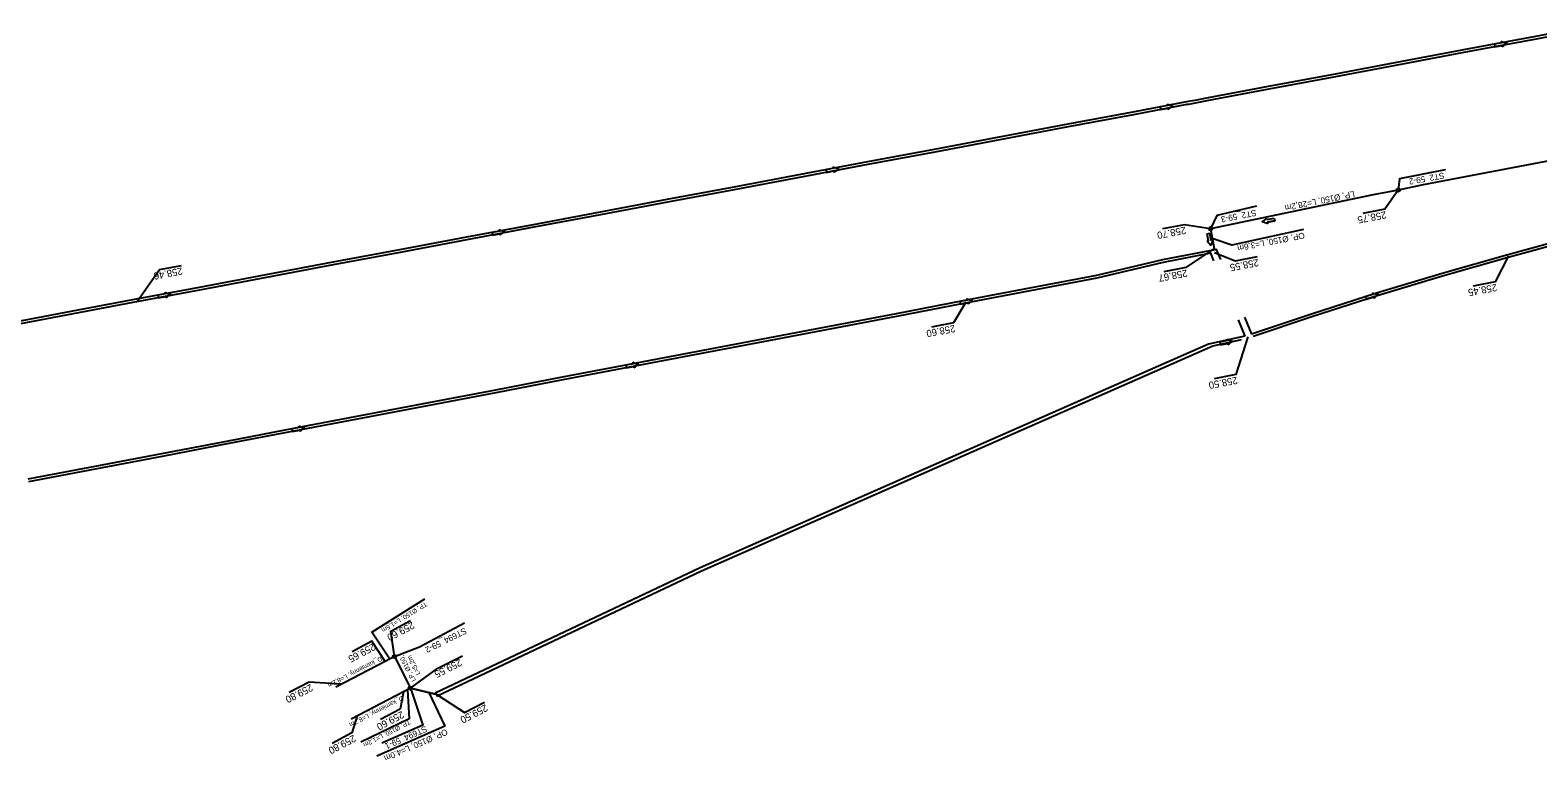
# Model space of a CAD drawing. Extents: x -1 to 65640748, y -22 to 5530284.
# Drawn here: x 6559740.8 to 6559962.5, y 5529060.7 to 5529168.1 of the extents above; entities that cross this region are included whole.
import ezdxf

# ---------------------------------------------------------------- set-up
doc = ezdxf.new("R2010")
doc.units = 0
for name, color, linetype in [('TOR_PROF-studnie i osadniki', 7, 'Continuous'), ('TOR_PS_ODW-drenaze', 7, 'Continuous'), ('TOR_PS_ODW-drenokolektory', 7, 'Continuous'), ('TOR_PS_ODW-kolektory', 7, 'Continuous'), ('TOR_PS_ODW-studnie PEHD', 7, 'Continuous'), ('TOR_PS_OPIS_O-opisy rurociagow', 7, 'Continuous'), ('TOR_PS_OPIS_O-opisy studni', 7, 'Continuous'), ('TOR_PS_OPIS_T-INFO', 7, 'Continuous'), ('TOR_PS_T-rowy otwarte umocnione', 7, 'Continuous')]:
    doc.layers.add(name, color=color, linetype=linetype)

msp = doc.modelspace()

# ---------------------------------------------------------------- linework, layer by layer
at = {"layer": 'TOR_PROF-studnie i osadniki'}
for centre, radius in [((6559941.99, 5529144.54), 0.25), ((6559941.99, 5529144.54), 0.125), ((6559914.39, 5529138.85), 0.25), ((6559914.39, 5529138.85), 0.125), ((6559794.35, 5529075.89), 0.25), ((6559794.35, 5529075.89), 0.125), ((6559796.7, 5529071.25), 0.25), ((6559796.7, 5529071.25), 0.125)]:
    msp.add_circle(centre, radius, dxfattribs=at)
at = {"layer": 'TOR_PS_ODW-drenaze'}
for p, q in [((6559792.99, 5529075.18), (6559785.73, 5529071.38)), ((6559795.69, 5529070.72), (6559787.98, 5529066.69))]:
    msp.add_line(p, q, dxfattribs=at)
at = {"layer": 'TOR_PS_ODW-drenokolektory'}
for p, q in [((6559794.35, 5529075.89), (6559792.99, 5529075.18)), ((6559796.7, 5529071.25), (6559795.69, 5529070.72))]:
    msp.add_line(p, q, dxfattribs=at)
for points in [[(6559999.28, 5529155.5), (6559945.65, 5529145.28), (6559941.99, 5529144.54)], [(6559941.99, 5529144.54), (6559938.33, 5529143.81), (6559914.39, 5529138.85)], [(6559794.35, 5529075.89), (6559796.7, 5529071.25), (6559796.7, 5529071.25)]]:
    msp.add_lwpolyline(points, dxfattribs=at)
at = {"layer": 'TOR_PS_ODW-kolektory'}
msp.add_line((6559796.7, 5529071.25), (6559800.58, 5529070.32), dxfattribs=at)
for points in [[(6559914.39, 5529138.85), (6559914.94, 5529135.94)], [(6559800.58, 5529070.32), (6559796.7, 5529071.25)]]:
    msp.add_lwpolyline(points, dxfattribs=at)
at = {"layer": 'TOR_PS_ODW-studnie PEHD'}
for centre, radius in [((6559941.99, 5529144.54), 0.25), ((6559941.99, 5529144.54), 0.112), ((6559794.35, 5529075.89), 0.25), ((6559794.35, 5529075.89), 0.112)]:
    msp.add_circle(centre, radius, dxfattribs=at)
at = {"layer": 'TOR_PS_OPIS_O-opisy rurociagow'}
for p, q in [((6559957.21, 5529166.2), (6559956.14, 5529166)), ((6559957.21, 5529166.2), (6559956.14, 5529166)), ((6559956.14, 5529166), (6559956.21, 5529165.61)), ((6559956.14, 5529166), (6559956.21, 5529165.61)), ((6559956.21, 5529165.61), (6559957.28, 5529165.81)), ((6559957.28, 5529165.81), (6559956.21, 5529165.61)), ((6559908.07, 5529156.97), (6559907, 5529156.77)), ((6559908.07, 5529156.97), (6559907, 5529156.77)), ((6559907, 5529156.77), (6559907.07, 5529156.37)), ((6559907, 5529156.77), (6559907.07, 5529156.37)), ((6559907.07, 5529156.37), (6559908.14, 5529156.58)), ((6559908.14, 5529156.58), (6559907.07, 5529156.37)), ((6559858.93, 5529147.74), (6559857.86, 5529147.53)), ((6559858.93, 5529147.74), (6559857.86, 5529147.53)), ((6559857.86, 5529147.53), (6559857.93, 5529147.14)), ((6559857.86, 5529147.53), (6559857.93, 5529147.14)), ((6559857.93, 5529147.14), (6559859, 5529147.34)), ((6559859, 5529147.34), (6559857.93, 5529147.14)), ((6559922.68, 5529140.19), (6559923.75, 5529140.41)), ((6559922.68, 5529140.19), (6559923.75, 5529140.41)), ((6559923.83, 5529140.02), (6559922.76, 5529139.8)), ((6559922.76, 5529139.8), (6559923.83, 5529140.02)), ((6559923.75, 5529140.41), (6559923.83, 5529140.02)), ((6559923.75, 5529140.41), (6559923.83, 5529140.02)), ((6559809.79, 5529138.5), (6559808.72, 5529138.3)), ((6559809.79, 5529138.5), (6559808.72, 5529138.3)), ((6559808.72, 5529138.3), (6559808.79, 5529137.91)), ((6559808.72, 5529138.3), (6559808.79, 5529137.91)), ((6559808.79, 5529137.91), (6559809.86, 5529138.11)), ((6559809.86, 5529138.11), (6559808.79, 5529137.91)), ((6559913.89, 5529138.09), (6559914.28, 5529138.17)), ((6559913.89, 5529138.09), (6559914.28, 5529138.17)), ((6559914.11, 5529137.02), (6559913.89, 5529138.09)), ((6559914.11, 5529137.02), (6559913.89, 5529138.09)), ((6559914.28, 5529138.17), (6559914.5, 5529137.1)), ((6559914.5, 5529137.1), (6559914.28, 5529138.17)), ((6559760.65, 5529129.27), (6559759.58, 5529129.07)), ((6559760.65, 5529129.27), (6559759.58, 5529129.07)), ((6559759.58, 5529129.07), (6559759.65, 5529128.68)), ((6559759.58, 5529129.07), (6559759.65, 5529128.68)), ((6559759.65, 5529128.68), (6559760.72, 5529128.88)), ((6559760.72, 5529128.88), (6559759.65, 5529128.68)), ((6559878.6, 5529128.34), (6559877.52, 5529128.13)), ((6559878.6, 5529128.34), (6559877.52, 5529128.13)), ((6559877.52, 5529128.13), (6559877.6, 5529127.74)), ((6559877.52, 5529128.13), (6559877.6, 5529127.74)), ((6559877.6, 5529127.74), (6559878.67, 5529127.94)), ((6559878.67, 5529127.94), (6559877.6, 5529127.74)), ((6559938.29, 5529129.19), (6559937.25, 5529128.87)), ((6559938.29, 5529129.19), (6559937.25, 5529128.87)), ((6559937.25, 5529128.87), (6559937.36, 5529128.49)), ((6559937.25, 5529128.87), (6559937.36, 5529128.49)), ((6559937.36, 5529128.49), (6559938.41, 5529128.8)), ((6559938.41, 5529128.8), (6559937.36, 5529128.49)), ((6559916.85, 5529122.38), (6559915.78, 5529122.17)), ((6559916.85, 5529122.38), (6559915.78, 5529122.17)), ((6559915.78, 5529122.17), (6559915.85, 5529121.78)), ((6559915.78, 5529122.17), (6559915.85, 5529121.78)), ((6559915.85, 5529121.78), (6559916.92, 5529121.98)), ((6559916.92, 5529121.98), (6559915.85, 5529121.78)), ((6559829.48, 5529118.97), (6559828.41, 5529118.77)), ((6559829.48, 5529118.97), (6559828.41, 5529118.77)), ((6559828.41, 5529118.77), (6559828.48, 5529118.37)), ((6559828.41, 5529118.77), (6559828.48, 5529118.37)), ((6559828.48, 5529118.37), (6559829.56, 5529118.58)), ((6559829.56, 5529118.58), (6559828.48, 5529118.37)), ((6559780.37, 5529109.61), (6559779.29, 5529109.4)), ((6559780.37, 5529109.61), (6559779.29, 5529109.4)), ((6559779.29, 5529109.4), (6559779.37, 5529109.01)), ((6559779.29, 5529109.4), (6559779.37, 5529109.01)), ((6559779.37, 5529109.01), (6559780.44, 5529109.21)), ((6559780.44, 5529109.21), (6559779.37, 5529109.01))]:
    msp.add_line(p, q, dxfattribs=at)
for points in [[(6559957.16, 5529166.42), (6559957.16, 5529166.42)], [(6559957.32, 5529165.59), (6559957.32, 5529165.59)], [(6559908.02, 5529157.19), (6559908.02, 5529157.19)], [(6559908.18, 5529156.35), (6559908.18, 5529156.35)], [(6559858.88, 5529147.96), (6559858.88, 5529147.96)], [(6559859.04, 5529147.12), (6559859.04, 5529147.12)], [(6559809.74, 5529138.72), (6559809.74, 5529138.72)], [(6559922.65, 5529140.42), (6559922.65, 5529140.42)], [(6559922.81, 5529139.58), (6559922.81, 5529139.58)], [(6559809.9, 5529137.89), (6559809.9, 5529137.89)], [(6559913.89, 5529136.98), (6559913.89, 5529136.98)], [(6559914.72, 5529137.16), (6559914.72, 5529137.16)], [(6559760.6, 5529129.49), (6559760.6, 5529129.49)], [(6559760.76, 5529128.66), (6559760.76, 5529128.66)], [(6559878.54, 5529128.56), (6559878.54, 5529128.56)], [(6559878.7, 5529127.72), (6559878.7, 5529127.72)], [(6559938.22, 5529129.4), (6559938.22, 5529129.4)], [(6559938.46, 5529128.59), (6559938.46, 5529128.59)], [(6559916.8, 5529122.59), (6559916.8, 5529122.59)], [(6559916.96, 5529121.76), (6559916.96, 5529121.76)], [(6559829.43, 5529119.19), (6559829.43, 5529119.19)], [(6559829.59, 5529118.36), (6559829.59, 5529118.36)], [(6559780.31, 5529109.82), (6559780.31, 5529109.82)], [(6559780.47, 5529108.99), (6559780.47, 5529108.99)]]:
    msp.add_lwpolyline(points, dxfattribs=at)
for centre, radius, start, end in [((6559959.09, 5529170.95), 4.92, 246.931, 257.3128), ((6559957.62, 5529166.41), 0.458, 179.0455, 207.5068), ((6559959.09, 5529170.95), 4.92, 246.931, 257.3128), ((6559957.62, 5529166.41), 0.458, 179.0455, 207.5068), ((6559957.74, 5529165.76), 0.458, 173.7749, 202.2361), ((6559957.74, 5529165.76), 0.458, 173.7749, 202.2361), ((6559960.75, 5529162.07), 4.92, 123.9689, 134.3507), ((6559960.75, 5529162.07), 4.92, 123.9689, 134.3507), ((6559909.95, 5529161.71), 4.92, 246.931, 257.3128), ((6559908.48, 5529157.18), 0.458, 179.0455, 207.5068), ((6559909.95, 5529161.71), 4.92, 246.931, 257.3128), ((6559908.48, 5529157.18), 0.458, 179.0455, 207.5068), ((6559908.6, 5529156.53), 0.458, 173.7749, 202.2361), ((6559908.6, 5529156.53), 0.458, 173.7749, 202.2361), ((6559911.61, 5529152.84), 4.92, 123.9689, 134.3507), ((6559911.61, 5529152.84), 4.92, 123.9689, 134.3507), ((6559860.81, 5529152.48), 4.92, 246.931, 257.3128), ((6559859.34, 5529147.95), 0.458, 179.0455, 207.5068), ((6559860.81, 5529152.48), 4.92, 246.931, 257.3128), ((6559859.34, 5529147.95), 0.458, 179.0455, 207.5068), ((6559862.47, 5529143.6), 4.92, 123.9689, 134.3507), ((6559862.47, 5529143.6), 4.92, 123.9689, 134.3507), ((6559859.46, 5529147.29), 0.458, 173.7749, 202.2361), ((6559859.46, 5529147.29), 0.458, 173.7749, 202.2361), ((6559811.67, 5529143.25), 4.92, 246.931, 257.3128), ((6559810.2, 5529138.72), 0.458, 179.0455, 207.5068), ((6559811.67, 5529143.25), 4.92, 246.931, 257.3128), ((6559810.2, 5529138.72), 0.458, 179.0455, 207.5068), ((6559919.16, 5529143.89), 4.92, 304.7037, 315.0855), ((6559919.16, 5529143.89), 4.92, 304.7037, 315.0855), ((6559920.95, 5529135.03), 4.92, 67.6658, 78.0476), ((6559920.95, 5529135.03), 4.92, 67.6658, 78.0476), ((6559922.23, 5529140.24), 0.458, 354.5097, 22.9709), ((6559922.23, 5529140.24), 0.458, 354.5097, 22.9709), ((6559922.36, 5529139.58), 0.458, 359.7803, 28.2416), ((6559922.36, 5529139.58), 0.458, 359.7803, 28.2416), ((6559810.32, 5529138.06), 0.458, 173.7749, 202.2361), ((6559810.32, 5529138.06), 0.458, 173.7749, 202.2361), ((6559813.33, 5529134.37), 4.92, 123.9689, 134.3507), ((6559813.33, 5529134.37), 4.92, 123.9689, 134.3507), ((6559914.07, 5529136.56), 0.458, 84.7749, 113.2361), ((6559914.07, 5529136.56), 0.458, 84.7749, 113.2361), ((6559910.43, 5529133.49), 4.92, 34.9689, 45.3507), ((6559910.43, 5529133.49), 4.92, 34.9689, 45.3507), ((6559919.28, 5529135.31), 4.92, 157.931, 168.3128), ((6559919.28, 5529135.31), 4.92, 157.931, 168.3128), ((6559914.72, 5529136.7), 0.458, 90.0456, 118.5068), ((6559914.72, 5529136.7), 0.458, 90.0456, 118.5068), ((6559762.53, 5529134.01), 4.92, 246.931, 257.3128), ((6559761.06, 5529129.48), 0.458, 179.0455, 207.5068), ((6559762.53, 5529134.01), 4.92, 246.931, 257.3128), ((6559761.06, 5529129.48), 0.458, 179.0455, 207.5068), ((6559761.18, 5529128.83), 0.458, 173.7749, 202.2361), ((6559761.18, 5529128.83), 0.458, 173.7749, 202.2361), ((6559764.19, 5529125.14), 4.92, 123.9689, 134.3507), ((6559764.19, 5529125.14), 4.92, 123.9689, 134.3507), ((6559880.46, 5529133.08), 4.92, 247.0634, 257.4452), ((6559879, 5529128.55), 0.458, 179.178, 207.6392), ((6559880.46, 5529133.08), 4.92, 247.0634, 257.4452), ((6559879, 5529128.55), 0.458, 179.178, 207.6392), ((6559879.13, 5529127.9), 0.458, 173.9073, 202.3686), ((6559879.13, 5529127.9), 0.458, 173.9073, 202.3686), ((6559882.15, 5529124.21), 4.92, 124.1013, 134.4831), ((6559882.15, 5529124.21), 4.92, 124.1013, 134.4831), ((6559939.65, 5529134.1), 4.92, 253.0777, 263.4595), ((6559938.67, 5529129.44), 0.458, 185.1922, 213.6535), ((6559939.65, 5529134.1), 4.92, 253.0777, 263.4595), ((6559938.67, 5529129.44), 0.458, 185.1922, 213.6535), ((6559938.87, 5529128.8), 0.458, 179.9216, 208.3828), ((6559938.87, 5529128.8), 0.458, 179.9216, 208.3828), ((6559942.26, 5529125.46), 4.92, 130.1156, 140.4974), ((6559942.26, 5529125.46), 4.92, 130.1156, 140.4974), ((6559918.72, 5529127.12), 4.92, 247.0234, 257.4052), ((6559917.26, 5529122.59), 0.458, 179.138, 207.5992), ((6559918.72, 5529127.12), 4.92, 247.0234, 257.4052), ((6559917.26, 5529122.59), 0.458, 179.138, 207.5992), ((6559917.38, 5529121.93), 0.458, 173.8673, 202.3285), ((6559917.38, 5529121.93), 0.458, 173.8673, 202.3285), ((6559920.4, 5529118.25), 4.92, 124.0613, 134.4431), ((6559920.4, 5529118.25), 4.92, 124.0613, 134.4431), ((6559831.34, 5529123.72), 4.92, 247.086, 257.4679), ((6559829.89, 5529119.18), 0.458, 179.2006, 207.6618), ((6559831.34, 5529123.72), 4.92, 247.086, 257.4679), ((6559829.89, 5529119.18), 0.458, 179.2006, 207.6618), ((6559833.04, 5529114.85), 4.92, 124.1239, 134.5057), ((6559833.04, 5529114.85), 4.92, 124.1239, 134.5057), ((6559830.01, 5529118.53), 0.458, 173.9299, 202.3912), ((6559830.01, 5529118.53), 0.458, 173.9299, 202.3912), ((6559782.23, 5529114.35), 4.92, 247.086, 257.4679), ((6559780.77, 5529109.82), 0.458, 179.2006, 207.6618), ((6559782.23, 5529114.35), 4.92, 247.086, 257.4679), ((6559780.77, 5529109.82), 0.458, 179.2006, 207.6618), ((6559780.9, 5529109.16), 0.458, 173.9299, 202.3912), ((6559780.9, 5529109.16), 0.458, 173.9299, 202.3912), ((6559783.92, 5529105.48), 4.92, 124.1239, 134.5057), ((6559783.92, 5529105.48), 4.92, 124.1239, 134.5057)]:
    msp.add_arc(centre, radius, start, end, dxfattribs=at)
at = {"layer": 'TOR_PS_OPIS_T-INFO'}
for points in [[(6559948.91, 5529147.52), (6559948.91, 5529147.52), (6559942.2, 5529146.19), (6559941.99, 5529144.54)], [(6559941.99, 5529144.54), (6559940.02, 5529141.72), (6559936.78, 5529141.09)], [(6559921.14, 5529142.14), (6559915.3, 5529140.8), (6559914.39, 5529138.85)], [(6559914.39, 5529138.85), (6559910.55, 5529139.44), (6559907.32, 5529138.82)], [(6559928.09, 5529138.73), (6559917.55, 5529136.43), (6559914.66, 5529137.4)], [(6559914.94, 5529135.94), (6559910.76, 5529133.13), (6559907.53, 5529132.51)], [(6559921.24, 5529134.7), (6559918.01, 5529134.07), (6559914.98, 5529135.32)], [(6559958.2, 5529134.84), (6559956.28, 5529131.03), (6559953.05, 5529130.41)], [(6559756.61, 5529128.3), (6559759.82, 5529132.85), (6559763.05, 5529133.45)], [(6559878.39, 5529128.03), (6559876.61, 5529124.99), (6559873.37, 5529124.37)], [(6559919.86, 5529122.92), (6559918.14, 5529117.38), (6559914.91, 5529116.76)], [(6559793.67, 5529075.53), (6559791.05, 5529079.49), (6559798.83, 5529084.41)], [(6559794.35, 5529075.89), (6559793.83, 5529079.65), (6559796.74, 5529081.19)], [(6559794.35, 5529075.89), (6559798.05, 5529077.33), (6559804.67, 5529080.84)], [(6559792.99, 5529075.18), (6559791.02, 5529078.14), (6559788.12, 5529076.58)], [(6559796.7, 5529071.25), (6559800.75, 5529074.19), (6559804.38, 5529075.99)], [(6559786.57, 5529071.82), (6559781.81, 5529072.14), (6559778.88, 5529070.62)], [(6559796.28, 5529070.98), (6559796.52, 5529066.75), (6559789.44, 5529063.28)], [(6559799.38, 5529070.71), (6559801.76, 5529065.63), (6559791.79, 5529061.22)], [(6559795.69, 5529070.72), (6559795.2, 5529068.17), (6559792.3, 5529066.61)], [(6559796.7, 5529071.25), (6559798.52, 5529065.81), (6559792.51, 5529063.16)], [(6559800.58, 5529070.32), (6559804.68, 5529067.68), (6559807.61, 5529069.18)], [(6559788.87, 5529067.16), (6559788.11, 5529064.66), (6559785.21, 5529063.11)]]:
    msp.add_lwpolyline(points, dxfattribs=at)
at = {"layer": 'TOR_PS_T-rowy otwarte umocnione'}
for p, q in [((6559918.44, 5529125.46), (6559919.44, 5529123.03)), ((6559919.37, 5529125.84), (6559920.4, 5529123.33)), ((6559839.32, 5529088.93), (6559800.34, 5529070.49)), ((6559839.53, 5529088.48), (6559800.55, 5529070.03))]:
    msp.add_line(p, q, dxfattribs=at)
for points in [[(6559967.11, 5529168.06), (6559962.2, 5529167.14), (6559952.37, 5529165.29), (6559942.54, 5529163.45), (6559932.71, 5529161.6), (6559922.88, 5529159.75), (6559914.04, 5529158.09), (6559913.06, 5529157.91), (6559912.07, 5529157.72), (6559911.09, 5529157.54), (6559910.85, 5529157.49), (6559910.85, 5529157.49), (6559903.23, 5529156.06), (6559893.4, 5529154.21), (6559883.57, 5529152.37), (6559873.74, 5529150.52), (6559863.92, 5529148.67), (6559854.09, 5529146.83), (6559844.26, 5529144.98), (6559834.43, 5529143.13), (6559824.6, 5529141.29), (6559814.78, 5529139.44), (6559804.95, 5529137.59), (6559795.12, 5529135.75), (6559785.29, 5529133.9), (6559775.46, 5529132.05), (6559765.63, 5529130.21), (6559755.81, 5529128.36), (6559745.98, 5529126.51), (6559736.15, 5529124.67)], [(6559967.18, 5529167.67), (6559962.27, 5529166.75), (6559952.44, 5529164.9), (6559942.61, 5529163.05), (6559932.79, 5529161.21), (6559922.96, 5529159.36), (6559914.11, 5529157.7), (6559913.13, 5529157.51), (6559912.15, 5529157.33), (6559911.16, 5529157.14), (6559910.93, 5529157.1), (6559910.93, 5529157.1), (6559903.3, 5529155.67), (6559893.47, 5529153.82), (6559883.65, 5529151.97), (6559873.82, 5529150.13), (6559863.99, 5529148.28), (6559854.16, 5529146.43), (6559844.33, 5529144.59), (6559834.51, 5529142.74), (6559824.68, 5529140.89), (6559814.85, 5529139.05), (6559805.02, 5529137.2), (6559795.19, 5529135.35), (6559785.37, 5529133.51), (6559775.54, 5529131.66), (6559765.71, 5529129.81), (6559755.88, 5529127.97), (6559746.05, 5529126.12), (6559736.23, 5529124.28)], [(6560036.01, 5529153.59), (6560026.16, 5529151.86), (6560016.37, 5529149.81), (6560006.64, 5529147.46), (6559996.91, 5529145.06), (6559987.19, 5529142.65), (6559977.48, 5529140.18), (6559972.63, 5529138.92), (6559967.79, 5529137.64), (6559958.11, 5529135.01), (6559948.45, 5529132.25), (6559938.83, 5529129.35), (6559929.23, 5529126.29), (6559920.4, 5529123.33)], [(6560036.09, 5529153.19), (6560026.23, 5529151.47), (6560016.45, 5529149.42), (6560006.71, 5529147.07), (6559996.99, 5529144.67), (6559987.27, 5529142.25), (6559977.56, 5529139.79), (6559972.71, 5529138.53), (6559967.86, 5529137.25), (6559958.18, 5529134.62), (6559948.53, 5529131.86), (6559938.9, 5529128.95), (6559929.3, 5529125.89), (6559920.69, 5529123.01)], [(6559915.9, 5529134.32), (6559915.29, 5529135.8), (6559907.35, 5529134.29), (6559897.62, 5529131.96), (6559887.79, 5529130.09), (6559877.97, 5529128.22), (6559868.15, 5529126.34), (6559858.32, 5529124.47), (6559848.5, 5529122.6), (6559838.68, 5529120.73), (6559828.86, 5529118.85), (6559819.03, 5529116.98), (6559809.21, 5529115.11), (6559799.39, 5529113.23), (6559789.56, 5529111.36), (6559779.74, 5529109.49), (6559769.92, 5529107.61), (6559760.09, 5529105.74), (6559750.27, 5529103.87), (6559740.45, 5529101.99)], [(6559914.9, 5529134.13), (6559914.45, 5529135.23), (6559907.43, 5529133.89), (6559897.69, 5529131.56), (6559887.87, 5529129.69), (6559878.05, 5529127.82), (6559868.22, 5529125.95), (6559858.4, 5529124.08), (6559848.58, 5529122.21), (6559838.75, 5529120.33), (6559828.93, 5529118.46), (6559819.11, 5529116.59), (6559809.28, 5529114.71), (6559799.46, 5529112.84), (6559789.64, 5529110.97), (6559779.82, 5529109.09), (6559769.99, 5529107.22), (6559760.17, 5529105.35), (6559750.35, 5529103.47), (6559740.52, 5529101.6)], [(6559919.44, 5529123.03), (6559914.11, 5529121.84), (6559839.32, 5529088.93)], [(6559918.9, 5529122.5), (6559914.73, 5529121.57), (6559839.52, 5529088.47)]]:
    msp.add_lwpolyline(points, dxfattribs=at)

# ---------------------------------------------------------------- texts
at = {"layer": 'TOR_PS_OPIS_O-opisy rurociagow'}
for s, height, rotation, p in [('LP, Ø150, L=28,2m', 0.9, 191.5233, (6559935.5, 5529144.4)), ('OP, Ø150, L=3,6m', 0.9, 190.9766, (6559928.15, 5529138.31)), ('TP, Ø150, L=1,5m', 0.675, 211.569, (6559798.89, 5529083.96)), ('D_kamienny, L=8,2m', 0.675, 207.1194, (6559792.34, 5529075.93)), ('LP, Ø150,', 0.675, 116.9031, (6559797.53, 5529072.42)), ('L=5,2m', 0.675, 116.9031, (6559798.19, 5529073.35)), ('D_kamienny, L=8,7m', 0.675, 207.1194, (6559795.49, 5529070.12)), ('TP, Ø150, L=1,2m', 0.675, 207.1194, (6559796.5, 5529066.6)), ('OP, Ø150, L=4.0m', 0.9, 203.4617, (6559801.95, 5529065.28))]:
    msp.add_text(s, height=height, rotation=rotation, dxfattribs=at).set_placement(p)
at = {"layer": 'TOR_PS_OPIS_O-opisy studni'}
for s, rotation, p in [('ST2_59-2', 190.2065, (6559948.71, 5529147.13)), ('ST2_59-3', 191.069, (6559921.05, 5529141.65)), ('ST694_59-2', 206.7012, (6559804.69, 5529080.17)), ('ST694_59-1', 203.8808, (6559798.91, 5529065.73))]:
    msp.add_text(s, height=0.9, rotation=rotation, dxfattribs=at).set_placement(p)
at = {"layer": 'TOR_PS_OPIS_T-INFO'}
for s, rotation, p in [('258.75', 190.7159, (6559940.15, 5529141.42)), ('258.70', 190.7159, (6559910.68, 5529139.15)), ('258.55', 190.7159, (6559921.38, 5529134.4)), ('258.46', 190.7506, (6559763.09, 5529133.15)), ('258.67', 190.7159, (6559910.89, 5529132.84)), ('258.45', 190.7159, (6559956.42, 5529130.73)), ('258.60', 190.7159, (6559876.74, 5529124.69)), ('258.50', 190.7159, (6559918.27, 5529117.08)), ('259.60', 208.1279, (6559796.95, 5529081.06)), ('259.65', 208.0218, (6559791.23, 5529077.9)), ('259.55', 206.533, (6559803.95, 5529075.58)), ('259.80', 207.2235, (6559782.02, 5529071.89)), ('259.60', 208.0218, (6559795.42, 5529067.92)), ('259.50', 207.447, (6559807.74, 5529068.91)), ('259.80', 208.0218, (6559788.33, 5529064.42))]:
    msp.add_text(s, height=1.05, rotation=rotation, dxfattribs=at).set_placement(p)

doc.saveas('drawing.dxf')
